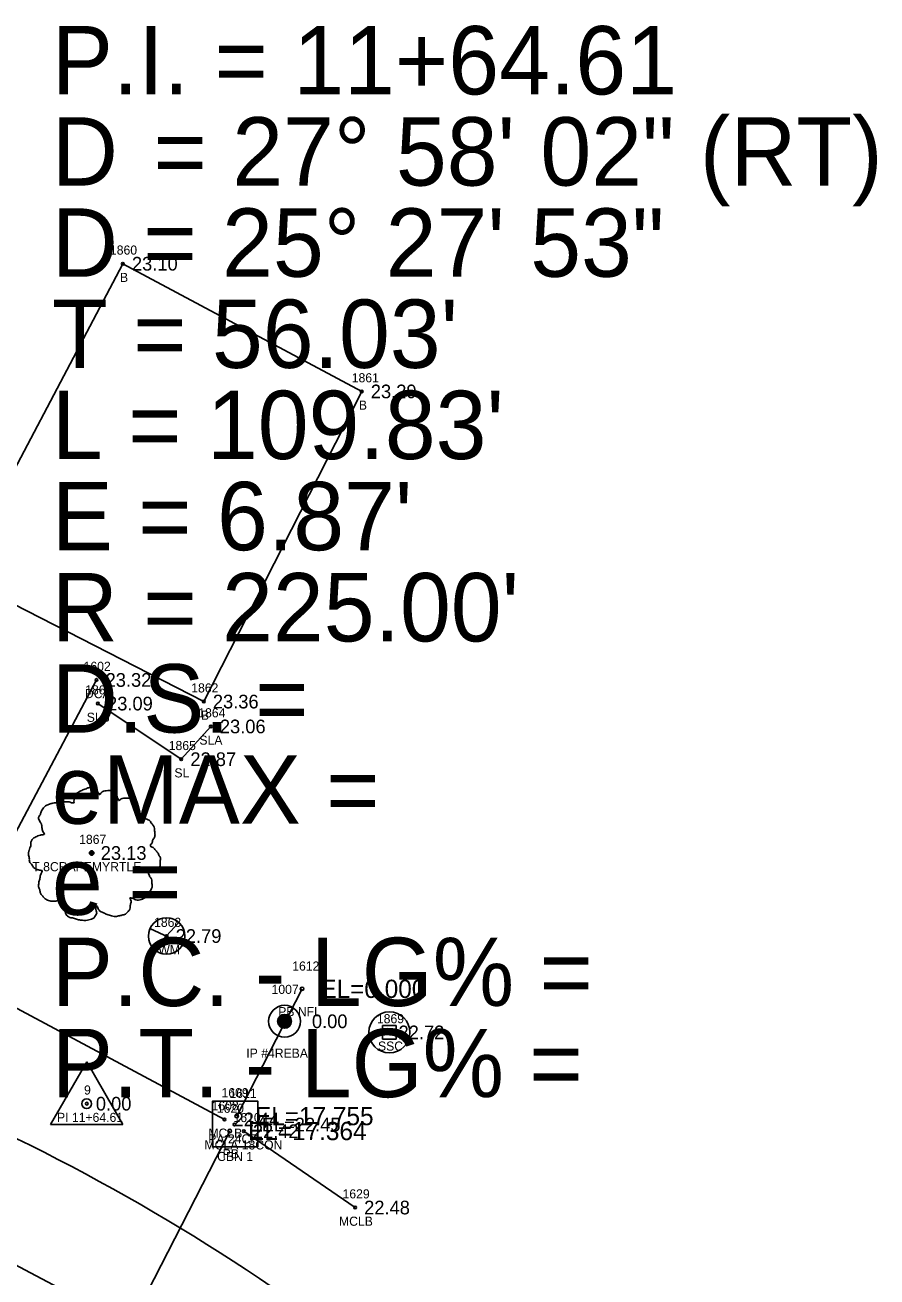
# Model space of a CAD drawing. Extents: x 2654414 to 2656963, y 761776 to 764965.
# Drawn here: x 2655764.1 to 2655857.5, y 762727.3 to 762864.6 of the extents above; entities that cross this region are included whole.
import ezdxf

# ---------------------------------------------------------------- set-up
doc = ezdxf.new("R2010")
doc.units = 0
for name, color, linetype in [('RD_EX_Bldg', 7, 'Continuous'), ('RD_EX_Bldg_txCode', 7, 'Continuous'), ('RD_EX_Conc', 7, 'Continuous'), ('RD_EX_Conc_txCode', 7, 'Continuous'), ('RD_EX_DR_Inlet', 7, 'Continuous'), ('RD_EX_DR_Inlet_txCode', 7, 'Continuous'), ('RD_EX_DR_Pipe', 7, 'Continuous'), ('RD_EX_DR_Pipe_txCode', 7, 'Continuous'), ('RD_EX_DV_Prop_txCode', 7, 'Continuous'), ('RD_EX_DV_PropPin', 7, 'Continuous'), ('RD_EX_TX_Bldg_ELEV', 7, 'Continuous'), ('RD_EX_TX_Conc_ELEV', 7, 'Continuous'), ('RD_EX_TX_DR_Inlet_ELEV', 7, 'Continuous'), ('RD_EX_TX_DV_Prop_ELEV', 7, 'Continuous'), ('RD_EX_TX_UT_ELEV', 7, 'Continuous'), ('RD_EX_TX_VEG_ELEV', 7, 'Continuous'), ('RD_EX_UT', 7, 'Continuous'), ('RD_EX_UT_txCode', 7, 'Continuous'), ('RD_EX_VEG', 7, 'Continuous'), ('RD_EX_VEG_txCode', 7, 'Continuous'), ('RD_HC_Cl', 7, 'Continuous'), ('RD_HC_Data', 7, 'Continuous'), ('RD_HC_Survey_ELEV', 7, 'Continuous'), ('RD_HC_txCode', 7, 'Continuous'), ('RD_SMD_Locator', 7, 'Continuous'), ('RD_TX_Pipe_ElevEX', 7, 'Continuous')]:
    doc.layers.add(name, color=color, linetype=linetype)

msp = doc.modelspace()

# ---------------------------------------------------------------- linework, layer by layer
at = {"layer": 'RD_EX_Bldg'}
msp.add_lwpolyline([(2655756.7, 762804.21), (2655774.78, 762838.43), (2655800.99, 762824.42), (2655783.66, 762790.4), (2655756.7, 762804.21)], dxfattribs=at)
at = {"layer": 'RD_EX_Conc'}
msp.add_line((2655788.05, 762743.27), (2655800.26, 762734.9), dxfattribs=at)
for points in [[(2655647.95, 762795.55), (2655656.5, 762788.85), (2655668.3, 762784.32), (2655695.43, 762778.05), (2655712.44, 762774.14), (2655737.03, 762767.62), (2655754.84, 762760.94), (2655757.41, 762759.82), (2655785.93, 762744.56)], [(2655771.89, 762792.77), (2655757.3, 762765.29), (2655757.75, 762760.7)], [(2655638.83, 762758.42), (2655640.65, 762759.07), (2655648.88, 762760.53), (2655656.27, 762760.57), (2655663.1, 762759.53), (2655700.27, 762751.26), (2655744.39, 762738.46), (2655772.67, 762723.5), (2655774.32, 762722.61)]]:
    msp.add_lwpolyline(points, dxfattribs=at)
at = {"layer": 'RD_EX_DR_Inlet'}
msp.add_line((2655789.61, 762741.55), (2655789.61, 762746.55), dxfattribs=at)
msp.add_lwpolyline([(2655789.61, 762741.55), (2655789.61, 762746.55), (2655784.61, 762746.55), (2655784.61, 762741.55)], close=True, dxfattribs=at)
at = {"layer": 'RD_EX_DR_Pipe'}
for p, q in [((2655787.28, 762744.93), (2655794.45, 762758.89)), ((2655775.82, 762722.4), (2655786.51, 762743.29))]:
    msp.add_line(p, q, dxfattribs=at)
at = {"layer": 'RD_EX_DV_PropPin'}
for p, q in [((2655791.79, 762755.13), (2655791.79, 762755.53)), ((2655791.83, 762755.03), (2655791.83, 762755.63)), ((2655791.86, 762754.96), (2655791.86, 762755.7)), ((2655791.9, 762754.9), (2655791.9, 762755.76)), ((2655791.93, 762754.86), (2655791.93, 762755.8)), ((2655791.97, 762754.82), (2655791.97, 762755.85)), ((2655792, 762754.78), (2655792, 762755.88)), ((2655792.04, 762754.75), (2655792.04, 762755.91)), ((2655792.07, 762754.72), (2655792.07, 762755.94)), ((2655792.11, 762754.7), (2655792.11, 762755.96)), ((2655792.14, 762754.67), (2655792.14, 762755.99)), ((2655792.18, 762754.65), (2655792.18, 762756.01)), ((2655792.21, 762754.64), (2655792.21, 762756.02)), ((2655792.25, 762754.62), (2655792.25, 762756.04)), ((2655792.28, 762754.61), (2655792.28, 762756.05)), ((2655792.32, 762754.6), (2655792.32, 762756.06)), ((2655792.35, 762754.59), (2655792.35, 762756.07)), ((2655792.39, 762754.58), (2655792.39, 762756.08)), ((2655792.42, 762754.58), (2655792.42, 762756.08)), ((2655792.46, 762754.57), (2655792.46, 762756.09)), ((2655792.49, 762754.57), (2655792.49, 762756.09)), ((2655792.53, 762754.57), (2655792.53, 762756.09)), ((2655792.56, 762754.57), (2655792.56, 762756.09)), ((2655792.6, 762754.57), (2655792.6, 762756.09)), ((2655792.63, 762754.58), (2655792.63, 762756.08)), ((2655792.67, 762754.58), (2655792.67, 762756.08)), ((2655792.7, 762754.59), (2655792.7, 762756.07)), ((2655792.74, 762754.6), (2655792.74, 762756.06)), ((2655792.77, 762754.61), (2655792.77, 762756.05)), ((2655792.81, 762754.62), (2655792.81, 762756.04)), ((2655792.85, 762754.64), (2655792.85, 762756.02)), ((2655792.88, 762754.65), (2655792.88, 762756.01)), ((2655792.92, 762754.67), (2655792.92, 762755.99)), ((2655792.95, 762754.7), (2655792.95, 762755.96)), ((2655792.99, 762754.72), (2655792.99, 762755.94)), ((2655793.02, 762754.75), (2655793.02, 762755.91)), ((2655793.06, 762754.78), (2655793.06, 762755.88)), ((2655793.09, 762754.82), (2655793.09, 762755.85)), ((2655793.13, 762754.86), (2655793.13, 762755.8)), ((2655793.16, 762754.9), (2655793.16, 762755.76)), ((2655793.2, 762754.96), (2655793.2, 762755.7)), ((2655793.23, 762755.03), (2655793.23, 762755.63)), ((2655793.27, 762755.13), (2655793.27, 762755.53))]:
    msp.add_line(p, q, dxfattribs=at)
for radius in [1.75, 0.761]:
    msp.add_circle((2655792.53, 762755.33), radius, dxfattribs=at)
at = {"layer": 'RD_EX_UT'}
for p, q in [((2655778.23, 762763.23), (2655780.9, 762766.12)), ((2655777.75, 762765.52), (2655781.38, 762763.81)), ((2655804.78, 762754.86), (2655803.28, 762754.86)), ((2655803.28, 762754.86), (2655803.28, 762753.36)), ((2655804.78, 762753.36), (2655804.78, 762754.86)), ((2655803.28, 762753.36), (2655804.78, 762753.36))]:
    msp.add_line(p, q, dxfattribs=at)
for centre, radius in [((2655779.58, 762764.68), 2), ((2655804.03, 762754.11), 2.25)]:
    msp.add_circle(centre, radius, dxfattribs=at)
at = {"layer": 'RD_EX_VEG'}
msp.add_lwpolyline([(2655784.43, 762787.67), (2655781.19, 762784.08), (2655772.05, 762790.18)], dxfattribs=at)
for centre, radius in [((2655771.36, 762773.79), 0.25), ((2655771.35, 762773.78), 0.0001)]:
    msp.add_circle(centre, radius, dxfattribs=at)
for points in [[(2655771.49, 762780.96), (2655771.19, 762780.99), (2655770.87, 762780.89), (2655770.62, 762780.79), (2655770.39, 762780.71), (2655770.17, 762780.61), (2655769.87, 762780.44), (2655769.64, 762780.24), (2655769.52, 762779.99), (2655769.47, 762779.76), (2655769.42, 762779.49), (2655769.42, 762779.31), (2655769.29, 762779.29), (2655769.14, 762779.31), (2655768.89, 762779.39), (2655768.64, 762779.39), (2655768.39, 762779.39), (2655768.04, 762779.36), (2655767.69, 762779.36), (2655767.42, 762779.31), (2655767.09, 762779.26), (2655766.72, 762779.14), (2655766.37, 762779.01), (2655766.07, 762778.76), (2655765.82, 762778.29), (2655765.69, 762777.94), (2655765.54, 762777.69), (2655765.69, 762777.24), (2655765.87, 762776.89), (2655765.89, 762776.69), (2655765.97, 762776.26), (2655766.07, 762776.04), (2655766.19, 762775.84), (2655766.12, 762775.81), (2655765.74, 762775.76), (2655765.44, 762775.66), (2655765.02, 762775.44), (2655764.79, 762775.21), (2655764.69, 762774.89), (2655764.67, 762774.54), (2655764.57, 762774.34), (2655764.49, 762774.06), (2655764.47, 762773.99), (2655764.42, 762773.66), (2655764.52, 762773.21), (2655764.54, 762772.86), (2655764.67, 762772.64), (2655764.82, 762772.46), (2655764.99, 762772.21), (2655765.39, 762771.99), (2655765.72, 762771.89), (2655765.92, 762771.87), (2655765.74, 762771.37), (2655765.69, 762771.02), (2655765.57, 762770.62), (2655765.57, 762770.54), (2655765.52, 762770.07), (2655765.67, 762769.74), (2655765.74, 762769.37), (2655765.92, 762769.14), (2655766.19, 762768.84), (2655766.52, 762768.62), (2655767.02, 762768.49), (2655767.42, 762768.52), (2655767.99, 762768.69), (2655768.24, 762768.77), (2655768.22, 762768.59), (2655768.24, 762768.22), (2655768.24, 762767.79), (2655768.39, 762767.47), (2655768.49, 762767.19), (2655768.64, 762766.94), (2655768.97, 762766.72), (2655769.37, 762766.64), (2655769.79, 762766.49), (2655770.24, 762766.42), (2655770.74, 762766.39), (2655771.34, 762766.54), (2655771.62, 762766.67), (2655771.72, 762766.84), (2655771.92, 762767.22), (2655771.87, 762767.44), (2655771.89, 762768.04), (2655771.99, 762767.87), (2655772.17, 762767.52), (2655772.67, 762767.22), (2655773.07, 762767.04), (2655773.54, 762766.89), (2655773.84, 762766.82), (2655774.31, 762766.89), (2655774.69, 762766.97), (2655775.06, 762767.09), (2655775.36, 762767.37), (2655775.54, 762767.64), (2655775.59, 762767.92), (2655775.66, 762768.29), (2655775.71, 762768.47)], [(2655775.71, 762768.47), (2655775.64, 762768.64), (2655775.59, 762768.89), (2655775.66, 762768.87), (2655775.84, 762768.82), (2655776.11, 762768.69), (2655776.34, 762768.62), (2655776.66, 762768.64), (2655776.94, 762768.74), (2655777.39, 762769.02), (2655777.66, 762769.49), (2655777.94, 762769.89), (2655778.01, 762770.22), (2655777.96, 762770.44), (2655777.94, 762770.94), (2655777.74, 762771.19), (2655777.69, 762771.32), (2655777.59, 762771.72), (2655777.66, 762771.77), (2655777.94, 762771.82), (2655778.31, 762771.94), (2655778.59, 762772.06), (2655778.81, 762772.24), (2655778.89, 762772.46), (2655778.86, 762772.86), (2655778.91, 762773.26), (2655778.84, 762773.41), (2655778.74, 762773.56), (2655778.66, 762773.76), (2655778.51, 762773.91), (2655778.41, 762774.06), (2655778.31, 762774.16), (2655778.19, 762774.31), (2655778.01, 762774.44), (2655777.86, 762774.49), (2655777.81, 762774.64), (2655777.96, 762774.84), (2655778.01, 762774.94), (2655778.04, 762775.16), (2655778.26, 762775.51), (2655778.31, 762775.91), (2655778.26, 762776.34), (2655778.21, 762776.61), (2655778.06, 762776.89), (2655777.86, 762777.14), (2655777.74, 762777.31), (2655777.56, 762777.44), (2655777.24, 762777.56), (2655776.99, 762777.61), (2655776.64, 762777.61), (2655776.44, 762777.66), (2655776.46, 762777.71), (2655776.46, 762777.86), (2655776.46, 762778.14), (2655776.39, 762778.59), (2655776.24, 762779.09), (2655776.24, 762779.11), (2655776.14, 762779.36), (2655775.91, 762779.56), (2655775.74, 762779.66), (2655775.54, 762779.79), (2655775.29, 762779.81), (2655774.99, 762779.81), (2655774.71, 762779.76), (2655774.51, 762779.66), (2655774.34, 762779.54), (2655774.26, 762779.69), (2655774.16, 762779.99), (2655774.11, 762780.14), (2655773.96, 762780.31), (2655773.74, 762780.51), (2655773.29, 762780.64), (2655772.67, 762780.56), (2655772.37, 762780.36), (2655772.22, 762780.19), (2655772.17, 762780.31), (2655771.97, 762780.51), (2655771.87, 762780.69), (2655771.69, 762780.81), (2655771.54, 762780.91), (2655771.44, 762780.96)]]:
    msp.add_spline(points, degree=3, dxfattribs=at)
at = {"layer": 'RD_HC_Cl'}
msp.add_arc((2655664.41, 762540.27), 225, 48.7013, 76.6686, dxfattribs=at)
at = {"layer": 'RD_HC_Data'}
for p, q in [((2655766.85, 762743.99), (2655770.82, 762750.87)), ((2655770.82, 762750.87), (2655774.79, 762743.99)), ((2655766.85, 762743.99), (2655774.79, 762743.99))]:
    msp.add_line(p, q, dxfattribs=at)
msp.add_circle((2655770.82, 762746.29), 0.529, dxfattribs=at)
at = {"layer": 'RD_SMD_Locator'}
for centre, radius in [((2655774.78, 762838.43), 0.15), ((2655800.99, 762824.42), 0.15), ((2655771.89, 762792.77), 0.15), ((2655772.05, 762790.18), 0.15), ((2655783.66, 762790.4), 0.15), ((2655784.43, 762787.67), 0.15), ((2655781.19, 762784.08), 0.15), ((2655771.36, 762773.79), 0.15), ((2655779.58, 762764.68), 0.15), ((2655794.45, 762758.89), 0.2), ((2655792.53, 762755.33), 0.15), ((2655804.03, 762754.11), 0.15), ((2655770.82, 762746.29), 0.15), ((2655785.93, 762744.56), 0.15), ((2655787.02, 762744), 0.15), ((2655787.28, 762744.93), 0.2), ((2655786.51, 762743.29), 0.2), ((2655788.05, 762743.27), 0.15), ((2655800.26, 762734.9), 0.15)]:
    msp.add_circle(centre, radius, dxfattribs=at)

# ---------------------------------------------------------------- texts
at = {"layer": 'RD_EX_Bldg_txCode'}
for s, p in [('1860', (2655773.37, 762839.43)), ('B', (2655774.47, 762836.43)), ('1861', (2655799.9, 762825.42)), ('B', (2655800.68, 762822.42)), ('1862', (2655782.29, 762791.4)), ('B', (2655783.35, 762788.4))]:
    msp.add_text(s, height=1, dxfattribs=at).set_placement(p)
at = {"layer": 'RD_EX_Conc_txCode'}
for s, p in [('1602', (2655770.48, 762793.77)), ('DCA', (2655770.62, 762790.77)), ('1608', (2655784.52, 762745.56)), ('1610', (2655786.93, 762744.27)), ('MCLB', (2655784.17, 762742.56)), ('MCLA 18CON', (2655783.74, 762741.27)), ('1629', (2655798.89, 762735.9)), ('MCLB', (2655798.5, 762732.9))]:
    msp.add_text(s, height=1, dxfattribs=at).set_placement(p)
at = {"layer": 'RD_EX_DR_Inlet_txCode'}
for s, p in [('1609', (2655785.61, 762747)), ('CBN 1', (2655785.13, 762740))]:
    msp.add_text(s, height=1, dxfattribs=at).set_placement(p)
at = {"layer": 'RD_EX_DR_Pipe_txCode'}
for s, p in [('1612', (2655793.37, 762760.89)), ('PB NFL', (2655791.83, 762755.89)), ('1611', (2655786.48, 762746.93)), ('1620', (2655785.1, 762745.29)), ('PA 24CP', (2655784.16, 762741.93)), ('PB', (2655785.73, 762740.29))]:
    msp.add_text(s, height=1, dxfattribs=at).set_placement(p)
at = {"layer": 'RD_EX_DV_Prop_txCode'}
for s, p in [('1007', (2655791.1, 762758.33)), ('IP #4REBAR', (2655788.33, 762751.33))]:
    msp.add_text(s, height=1, dxfattribs=at).set_placement(p)
at = {"layer": 'RD_EX_TX_Bldg_ELEV'}
for s, p in [('23.10', (2655775.78, 762837.68)), ('23.29', (2655801.99, 762823.67)), ('23.36', (2655784.66, 762789.65))]:
    msp.add_text(s, height=1.5, dxfattribs=at).set_placement(p)
at = {"layer": 'RD_EX_TX_Conc_ELEV'}
for s, p in [('23.32', (2655772.89, 762792.02)), ('22.44', (2655786.93, 762743.81)), ('22.42', (2655789.05, 762742.52)), ('22.48', (2655801.26, 762734.15))]:
    msp.add_text(s, height=1.5, dxfattribs=at).set_placement(p)
at = {"layer": 'RD_EX_TX_DR_Inlet_ELEV'}
msp.add_text('EL=22.45', height=1.5, dxfattribs=at).set_placement((2655790.02, 762743.25))
at = {"layer": 'RD_EX_TX_DV_Prop_ELEV'}
msp.add_text('0.00', height=1.5, dxfattribs=at).set_placement((2655795.53, 762754.58))
at = {"layer": 'RD_EX_TX_UT_ELEV'}
for s, p in [('22.79', (2655780.58, 762763.93)), ('22.72', (2655805.03, 762753.36))]:
    msp.add_text(s, height=1.5, dxfattribs=at).set_placement(p)
at = {"layer": 'RD_EX_TX_VEG_ELEV'}
for s, p in [('23.09', (2655773.05, 762789.43)), ('23.06', (2655785.43, 762786.92)), ('22.87', (2655782.19, 762783.33)), ('23.13', (2655772.36, 762773.04))]:
    msp.add_text(s, height=1.5, dxfattribs=at).set_placement(p)
at = {"layer": 'RD_EX_UT_txCode'}
for s, p in [('1868', (2655778.21, 762765.68)), ('WM', (2655778.67, 762762.68)), ('1869', (2655802.66, 762755.11)), ('SSC', (2655802.78, 762752.11))]:
    msp.add_text(s, height=1, dxfattribs=at).set_placement(p)
at = {"layer": 'RD_EX_VEG_txCode'}
for s, p in [('1866', (2655770.65, 762791.18)), ('1864', (2655783.06, 762788.67)), ('SLB', (2655770.82, 762788.18)), ('SLA', (2655783.18, 762785.67)), ('1865', (2655779.82, 762785.08)), ('SL', (2655780.44, 762782.08)), ('1867', (2655769.99, 762774.79)), ('T 8CRAPEMYRTLE', (2655764.85, 762771.79))]:
    msp.add_text(s, height=1, dxfattribs=at).set_placement(p)
at = {"layer": 'RD_HC_Data'}
for s, p in [('P.I. = 11+64.61', (2655767, 762857)), ('D', (2655767, 762847)), ('    = 27%%d 58\' 02" (RT)', (2655767, 762847)), ('D = 25%%d 27\' 53"', (2655767, 762837)), ("T = 56.03'", (2655767, 762827)), ("L = 109.83'", (2655767, 762817)), ("E = 6.87'", (2655767, 762807)), ("R = 225.00'", (2655767, 762797)), ('D.S. = ', (2655767, 762787)), ('eMAX = ', (2655767, 762777)), ('e = ', (2655767, 762767)), ('P.C. - LG% = ', (2655767, 762757)), ('P.T. - LG% = ', (2655767, 762747))]:
    msp.add_text(s, height=7.5, dxfattribs=at).set_placement(p)
at = {"layer": 'RD_HC_Survey_ELEV'}
msp.add_text('0.00', height=1.5, dxfattribs=at).set_placement((2655771.82, 762745.54))
at = {"layer": 'RD_HC_txCode'}
for s, p in [('9', (2655770.53, 762747.29)), ('PI 11+64.61', (2655767.56, 762744.29))]:
    msp.add_text(s, height=1, dxfattribs=at).set_placement(p)
at = {"layer": 'RD_TX_Pipe_ElevEX'}
for s, p in [('EL=0.000', (2655796.45, 762757.89)), ('EL=17.755', (2655789.28, 762743.93)), ('EL=17.364', (2655788.51, 762742.29))]:
    msp.add_text(s, height=2, dxfattribs=at).set_placement(p)

doc.saveas('drawing.dxf')
